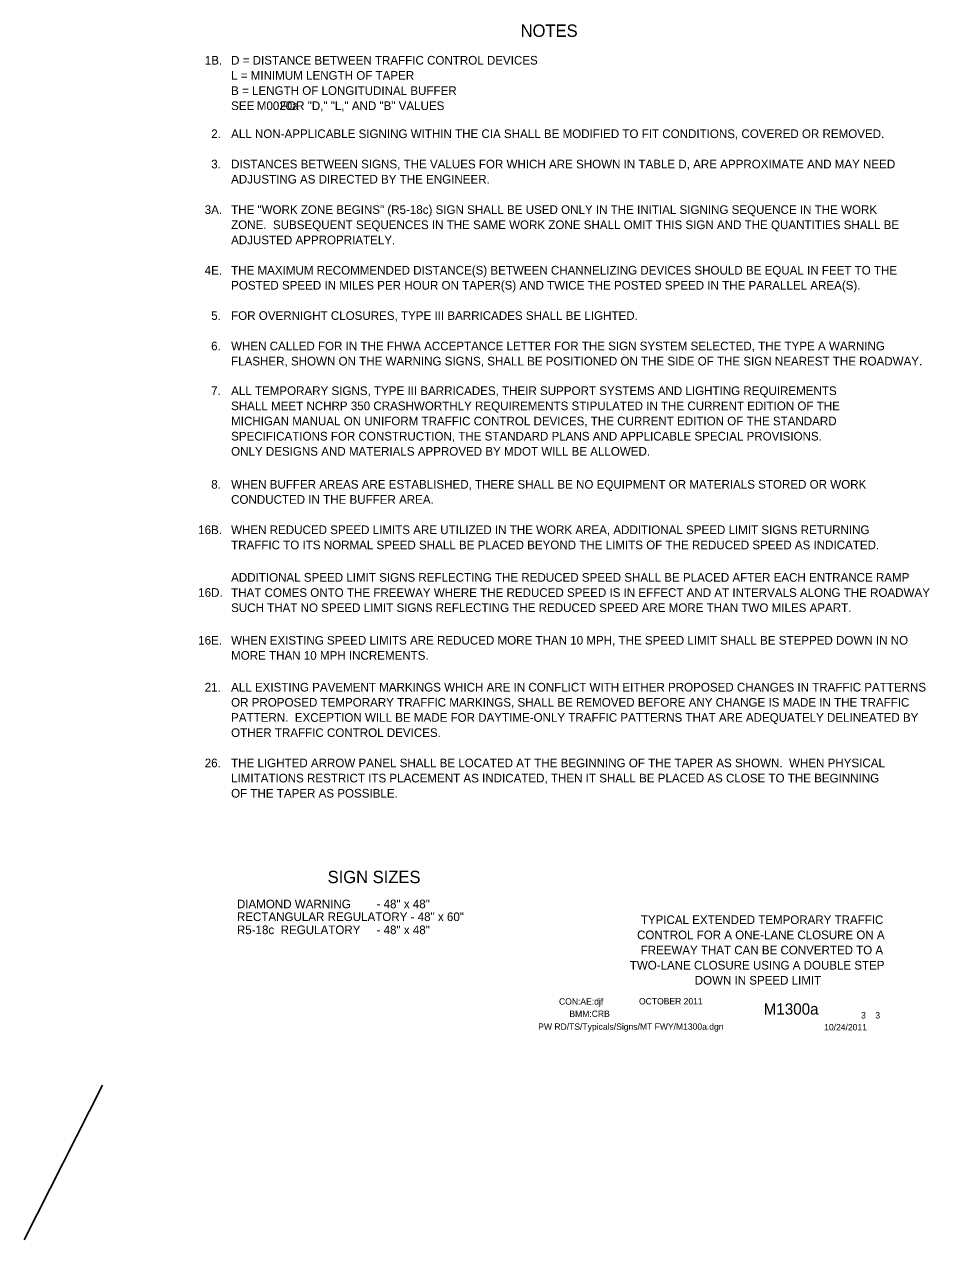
# Model space of a CAD drawing. Extents: x 16590 to 19508, y 5703 to 6974.
# Drawn here: x 18630 to 19508, y 5730 to 6909 of the extents above; entities that cross this region are included whole.
import ezdxf

# ---------------------------------------------------------------- set-up
doc = ezdxf.new("R2010")
doc.units = 0
for name, color, linetype in [('BORDER', 7, 'Continuous'), ('BORDER_SIGNAL_WO', 7, 'Continuous'), ('TYPICAL_TEXT_DIMEN_PR', 7, 'Continuous')]:
    doc.layers.add(name, color=color, linetype=linetype)

msp = doc.modelspace()

# ---------------------------------------------------------------- linework, layer by layer
at = {"layer": 'TYPICAL_TEXT_DIMEN_PR'}
msp.add_line((18705.8, 5880), (18630.1, 5730.1), dxfattribs=at)

# ---------------------------------------------------------------- texts
at = {"layer": 'BORDER'}
for s, p in [('TYPICAL EXTENDED TEMPORARY TRAFFIC', (19228.1, 6036.3)), ('CONTROL FOR A ONE-LANE CLOSURE ON A', (19224.4, 6021.6)), ('FREEWAY THAT CAN BE CONVERTED TO A', (19227.9, 6006.9)), ('TWO-LANE CLOSURE USING A DOUBLE STEP ', (19217.4, 5992.2)), ('DOWN IN SPEED LIMIT', (19280.4, 5977.6))]:
    msp.add_text(s, height=8.373, dxfattribs=at).set_placement(p)
at = {"layer": 'BORDER_SIGNAL_WO'}
for s, height, p in [('CON:AE:djf  ', 6.2, (19148.7, 5958.1)), ('    OCTOBER 2011    ', 6.2, (19217.1, 5958.3)), ('    M1300a   ', 11, (19330.9, 5948.4)), ('BMM:CRB   ', 6.2, (19158.8, 5946.2)), (' 3    3 ', 6.2, (19439.4, 5944.7)), ('PW RD/TS/Typicals/Signs/MT FWY/M1300a.dgn      ', 6.2, (19128.6, 5933.7)), ('10/24/2011    ', 6.2, (19405.9, 5933.1))]:
    msp.add_text(s, height=height, dxfattribs=at).set_placement(p)
at = {"layer": 'TYPICAL_TEXT_DIMEN_PR'}
for s, height, p in [('NOTES', 12, (19111.5, 6897)), ('1B.', 8.4, (18805.2, 6870.1)), ('D = DISTANCE BETWEEN TRAFFIC CONTROL DEVICES', 8.4, (18830.7, 6870.1)), ('L = MINIMUM LENGTH OF TAPER', 8.4, (18830.7, 6855.4)), ('B = LENGTH OF LONGITUDINAL BUFFER', 8.4, (18830.7, 6840.7)), ('SEE        FOR "D," "L," AND "B" VALUES', 8.4, (18830.7, 6826)), ('M0020a', 8.4, (18855.6, 6826)), ('2.', 8.4, (18811.4, 6798.8)), ('ALL NON-APPLICABLE SIGNING WITHIN THE CIA SHALL BE MODIFIED TO FIT CONDITIONS, COVERED OR REMOVED.', 8.4, (18830.7, 6798.8)), ('3.', 8.4, (18811.4, 6769.4)), ('DISTANCES BETWEEN SIGNS, THE VALUES FOR WHICH ARE SHOWN IN TABLE D, ARE APPROXIMATE AND MAY NEED', 8.4, (18830.7, 6769.4)), ('ADJUSTING AS DIRECTED BY THE ENGINEER.', 8.4, (18830.7, 6754.7)), ('3A.', 8.4, (18805.1, 6725.2)), ('THE "WORK ZONE BEGINS" (R5-18c) SIGN SHALL BE USED ONLY IN THE INITIAL SIGNING SEQUENCE IN THE WORK', 8.4, (18830.7, 6725.2)), ('ZONE.  SUBSEQUENT SEQUENCES IN THE SAME WORK ZONE SHALL OMIT THIS SIGN AND THE QUANTITIES SHALL BE', 8.4, (18830.7, 6710.5)), ('ADJUSTED APPROPRIATELY.', 8.4, (18830.7, 6695.8)), ('4E.', 8.4, (18805.1, 6666.4)), ('THE MAXIMUM RECOMMENDED DISTANCE(S) BETWEEN CHANNELIZING DEVICES SHOULD BE EQUAL IN FEET TO THE', 8.4, (18830.7, 6666.4)), ('POSTED SPEED IN MILES PER HOUR ON TAPER(S) AND TWICE THE POSTED SPEED IN THE PARALLEL AREA(S).', 8.4, (18830.7, 6651.8)), ('5.', 8.4, (18811.4, 6622.4)), ('FOR OVERNIGHT CLOSURES, TYPE III BARRICADES SHALL BE LIGHTED. ', 8.4, (18830.7, 6622.4)), ('6.', 8.4, (18811.3, 6592.9)), ('WHEN CALLED FOR IN THE FHWA ACCEPTANCE LETTER FOR THE SIGN SYSTEM SELECTED, THE TYPE A WARNING ', 8.4, (18830.7, 6592.9)), ('FLASHER, SHOWN ON THE WARNING SIGNS, SHALL BE POSITIONED ON THE SIDE OF THE SIGN NEAREST THE ROADWAY.', 8.4, (18830.7, 6578.2)), ('7.', 8.4, (18811.3, 6549.5)), ('ALL TEMPORARY SIGNS, TYPE III BARRICADES, THEIR SUPPORT SYSTEMS AND LIGHTING REQUIREMENTS', 8.4, (18830.7, 6549.5)), ('SHALL MEET NCHRP 350 CRASHWORTHLY REQUIREMENTS STIPULATED IN THE CURRENT EDITION OF THE', 8.4, (18830.7, 6534.8)), ('MICHIGAN MANUAL ON UNIFORM TRAFFIC CONTROL DEVICES, THE CURRENT EDITION OF THE STANDARD', 8.4, (18830.7, 6520.1)), ('SPECIFICATIONS FOR CONSTRUCTION, THE STANDARD PLANS AND APPLICABLE SPECIAL PROVISIONS.', 8.4, (18830.7, 6505.4)), ('ONLY DESIGNS AND MATERIALS APPROVED BY MDOT WILL BE ALLOWED.', 8.4, (18830.7, 6490.7)), ('8.', 8.4, (18811.4, 6458.7)), ('WHEN BUFFER AREAS ARE ESTABLISHED, THERE SHALL BE NO EQUIPMENT OR MATERIALS STORED OR WORK     ', 8.4, (18830.7, 6458.7)), ('CONDUCTED IN THE BUFFER AREA.', 8.4, (18830.7, 6444)), ('16B.', 8.4, (18798.8, 6414.6)), ('WHEN REDUCED SPEED LIMITS ARE UTILIZED IN THE WORK AREA, ADDITIONAL SPEED LIMIT SIGNS RETURNING', 8.4, (18830.7, 6414.6)), ('TRAFFIC TO ITS NORMAL SPEED SHALL BE PLACED BEYOND THE LIMITS OF THE REDUCED SPEED AS INDICATED.', 8.4, (18830.7, 6399.9)), ('ADDITIONAL SPEED LIMIT SIGNS REFLECTING THE REDUCED SPEED SHALL BE PLACED AFTER EACH ENTRANCE RAMP', 8.4, (18830.7, 6368.4)), ('16D.', 8.4, (18798.8, 6353.8)), ('THAT COMES ONTO THE FREEWAY WHERE THE REDUCED SPEED IS IN EFFECT AND AT INTERVALS ALONG THE ROADWAY', 8.4, (18830.7, 6353.7)), ('SUCH THAT NO SPEED LIMIT SIGNS REFLECTING THE REDUCED SPEED ARE MORE THAN TWO MILES APART.', 8.4, (18830.7, 6339)), ('16E.', 8.4, (18798.8, 6307.4)), ('WHEN EXISTING SPEED LIMITS ARE REDUCED MORE THAN 10 MPH, THE SPEED LIMIT SHALL BE STEPPED DOWN IN NO', 8.4, (18830.7, 6307.4)), ('MORE THAN 10 MPH INCREMENTS.', 8.4, (18830.7, 6292.7)), ('21.', 8.4, (18805.1, 6261.9)), ('ALL EXISTING PAVEMENT MARKINGS WHICH ARE IN CONFLICT WITH EITHER PROPOSED CHANGES IN TRAFFIC PATTERNS', 8.4, (18830.7, 6261.9)), ('OR PROPOSED TEMPORARY TRAFFIC MARKINGS, SHALL BE REMOVED BEFORE ANY CHANGE IS MADE IN THE TRAFFIC', 8.4, (18830.7, 6247.2)), ('PATTERN.  EXCEPTION WILL BE MADE FOR DAYTIME-ONLY TRAFFIC PATTERNS THAT ARE ADEQUATELY DELINEATED BY', 8.4, (18830.7, 6232.5)), ('OTHER TRAFFIC CONTROL DEVICES.', 8.4, (18830.7, 6217.8)), ('26.', 8.4, (18805.1, 6188.4)), ('THE LIGHTED ARROW PANEL SHALL BE LOCATED AT THE BEGINNING OF THE TAPER AS SHOWN.  WHEN PHYSICAL', 8.4, (18830.7, 6188.4)), ('LIMITATIONS RESTRICT ITS PLACEMENT AS INDICATED, THEN IT SHALL BE PLACED AS CLOSE TO THE BEGINNING', 8.4, (18830.7, 6173.7)), ('OF THE TAPER AS POSSIBLE.', 8.4, (18830.7, 6159)), ('SIGN SIZES', 12, (18924.3, 6076)), ('DIAMOND WARNING        - 48" x 48"', 8.4, (18836.3, 6051.6)), ('RECTANGULAR REGULATORY - 48" x 60"', 8.4, (18836.3, 6039.2)), ('R5-18c  REGULATORY     - 48" x 48"', 8.4, (18836.3, 6026.5))]:
    msp.add_text(s, height=height, dxfattribs=at).set_placement(p)

doc.saveas('drawing.dxf')
